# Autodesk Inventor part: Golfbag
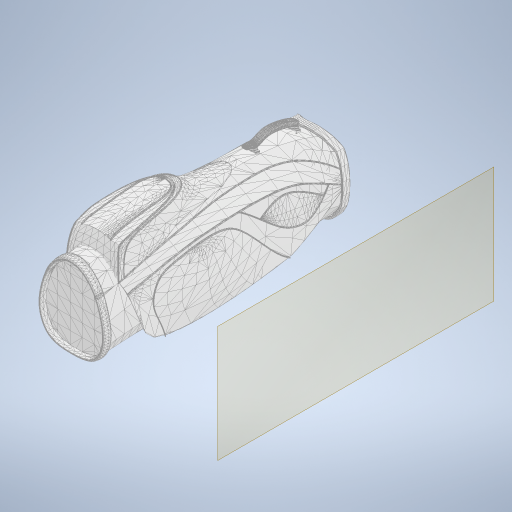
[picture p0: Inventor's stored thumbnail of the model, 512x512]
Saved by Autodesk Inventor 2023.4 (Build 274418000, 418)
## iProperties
Created: 2025-03
Part Number: Golfbag
Material: Générique
Document SubType Name: Modeling
Designer: bruno
Density: 1 g/cm^3
Appearance: Par défaut
Author: bruno
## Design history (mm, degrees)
node "Golfbag_2017_2"
  node "FonctionMaillage1"
node "Plan de construction1"
other parameters: "d0" = 1489.075
